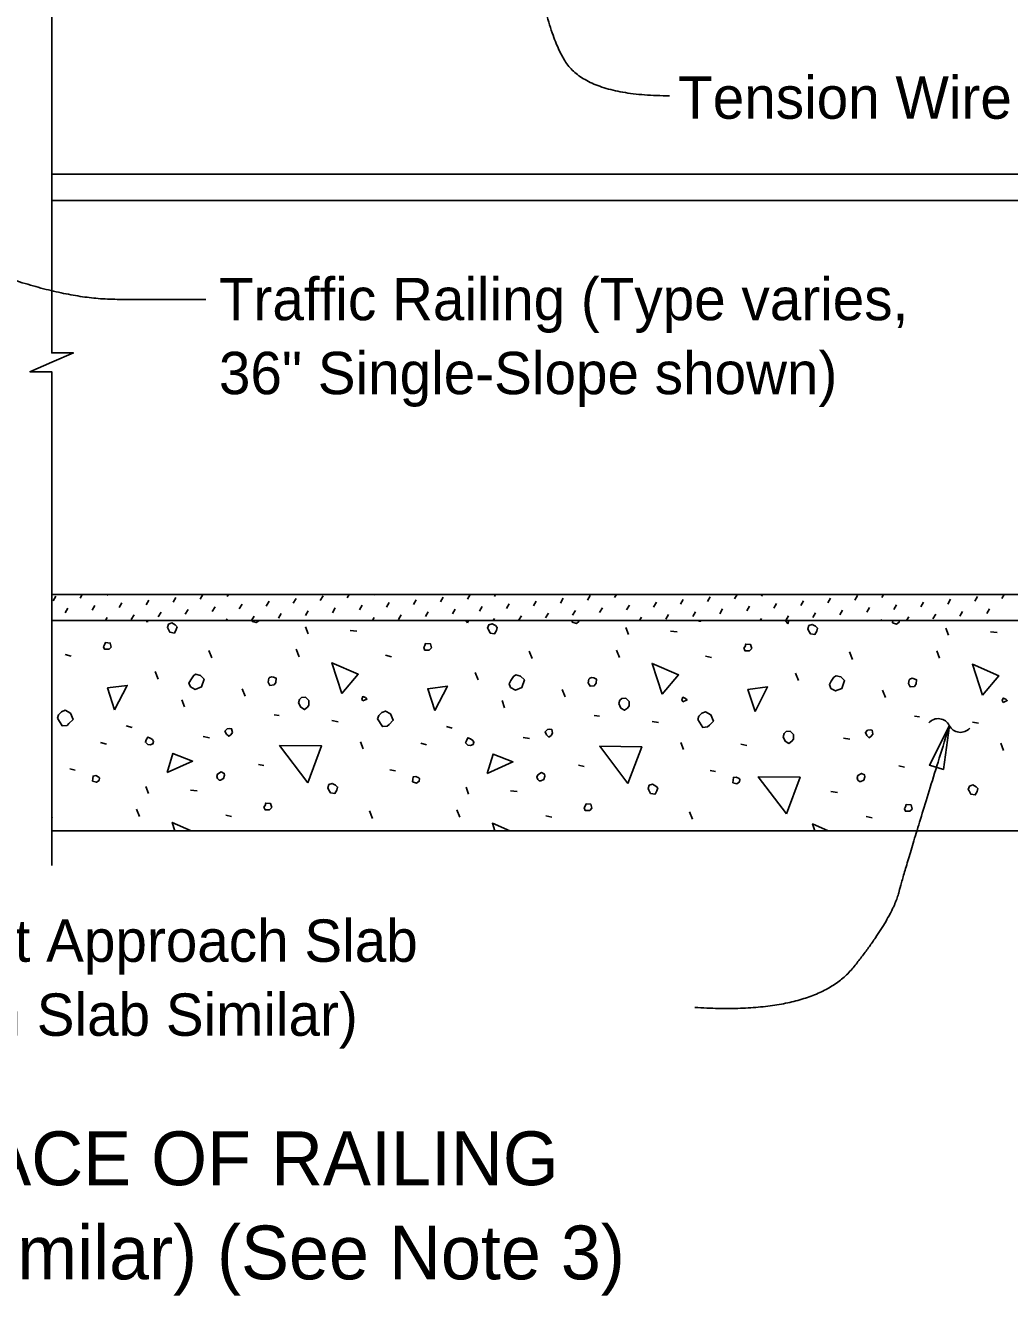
# Model space of a CAD drawing. Extents: x 0 to 41.1, y 0 to 25.9.
# Drawn here: x 16.13 to 20.81, y 10.89 to 16.93 of the extents above; entities that cross this region are included whole.
import ezdxf

# ---------------------------------------------------------------- set-up
doc = ezdxf.new("R2010")
doc.units = 0
for name, color, linetype in [('Dimension', 7, 'Continuous'), ('Miscellaneous', 7, 'Continuous'), ('SupstrConc', 7, 'Continuous'), ('TextStructures', 7, 'Continuous')]:
    doc.layers.add(name, color=color, linetype=linetype)

msp = doc.modelspace()

# ---------------------------------------------------------------- linework, layer by layer
at = {"layer": 'Dimension'}
msp.add_lwpolyline([(16.252, 17.2246), (16.252, 15.3737), (16.3553, 15.3737), (16.252, 15.3287), (16.1487, 15.2837), (16.252, 15.2837), (16.252, 12.9339)], dxfattribs=at)
msp.add_lwpolyline([(20.5246, 13.6005), (20.4289, 13.4122), (20.4962, 13.3912)], close=True, dxfattribs=at)
for centre, start, end in [((20.4706, 13.5736), 26.84133, 138.56855), ((20.577, 13.6275), 206.84133, 318.56855)]:
    msp.add_arc(centre, 0.0596, start, end, dxfattribs=at)
for points in [[(19.1927, 16.5972), (18.7949, 16.5972), (18.5909, 16.9342), (18.5297, 17.3911)], [(16.9853, 15.6282), (16.9154, 15.6282), (16.2159, 15.6282), (15.6583, 15.8852)], [(19.3131, 12.2588), (19.886, 12.2223), (20.2509, 12.679), (20.3172, 12.9363), (20.5245, 13.6004)]]:
    msp.add_open_spline(points, degree=2, dxfattribs=at)
at = {"layer": 'Miscellaneous'}
for p, q in [((16.2587, 14.1938), (16.2717, 14.2162)), ((16.3872, 14.2068), (16.3975, 14.2245)), ((16.5157, 14.2197), (16.5184, 14.2245)), ((16.8303, 14.1879), (16.8433, 14.2103)), ((16.9588, 14.2009), (16.9717, 14.2233)), ((17.0872, 14.2138), (17.0934, 14.2245)), ((17.5303, 14.195), (17.5433, 14.2174)), ((17.6588, 14.2079), (17.6684, 14.2245)), ((17.7873, 14.2209), (17.7893, 14.2245)), ((18.1019, 14.1891), (18.1149, 14.2115)), ((18.2304, 14.2021), (18.2433, 14.2244)), ((18.3588, 14.215), (18.3643, 14.2245)), ((18.6735, 14.1832), (18.6865, 14.2056)), ((18.802, 14.1962), (18.8149, 14.2186)), ((18.9304, 14.2091), (18.9393, 14.2245)), ((19.0589, 14.2221), (19.0603, 14.2245)), ((19.3735, 14.1903), (19.3865, 14.2127)), ((19.502, 14.2032), (19.5143, 14.2245)), ((19.6305, 14.2162), (19.6353, 14.2245)), ((19.9451, 14.1844), (19.9581, 14.2068)), ((20.0736, 14.1973), (20.0865, 14.2197)), ((20.202, 14.2103), (20.2103, 14.2245)), ((20.3305, 14.2233), (20.3312, 14.2245)), ((20.6452, 14.1914), (20.6581, 14.2138)), ((20.7736, 14.2044), (20.7852, 14.2245)), ((16.3165, 14.1361), (16.3294, 14.1584)), ((16.4449, 14.149), (16.4579, 14.1714)), ((16.5734, 14.162), (16.5864, 14.1844)), ((16.7019, 14.1749), (16.7148, 14.1973)), ((16.8881, 14.1302), (16.901, 14.1526)), ((17.0165, 14.1431), (17.0295, 14.1655)), ((17.145, 14.1561), (17.1579, 14.1785)), ((17.2734, 14.1691), (17.2864, 14.1914)), ((17.4019, 14.182), (17.4149, 14.2044)), ((17.4596, 14.1243), (17.4726, 14.1467)), ((17.5881, 14.1372), (17.6011, 14.1596)), ((17.7166, 14.1502), (17.7295, 14.1726)), ((17.845, 14.1632), (17.858, 14.1856)), ((17.9735, 14.1761), (17.9864, 14.1985)), ((18.1597, 14.1313), (18.1726, 14.1537)), ((18.2881, 14.1443), (18.3011, 14.1667)), ((18.4166, 14.1573), (18.4296, 14.1797)), ((18.545, 14.1702), (18.558, 14.1926)), ((18.7313, 14.1254), (18.7442, 14.1478)), ((18.8597, 14.1384), (18.8727, 14.1608)), ((18.9882, 14.1514), (19.0011, 14.1738)), ((19.1166, 14.1643), (19.1296, 14.1867)), ((19.2451, 14.1773), (19.258, 14.1997)), ((19.4313, 14.1325), (19.4443, 14.1549)), ((19.5597, 14.1455), (19.5727, 14.1679)), ((19.6882, 14.1584), (19.7012, 14.1808)), ((19.8167, 14.1714), (19.8296, 14.1938)), ((20.0029, 14.1266), (20.0158, 14.149)), ((20.1313, 14.1396), (20.1443, 14.162)), ((20.2598, 14.1526), (20.2727, 14.1749)), ((20.3882, 14.1655), (20.4012, 14.1879)), ((20.5167, 14.1785), (20.5297, 14.2009)), ((20.7029, 14.1337), (20.7159, 14.1561)), ((16.5075, 14.0995), (16.5157, 14.1137)), ((16.6311, 14.1042), (16.6441, 14.1266)), ((16.7596, 14.1172), (16.7726, 14.1396)), ((17.0825, 14.0995), (17.0872, 14.1078)), ((17.2034, 14.0995), (17.2157, 14.1207)), ((17.3312, 14.1113), (17.3441, 14.1337)), ((17.6574, 14.0995), (17.6588, 14.1019)), ((17.7784, 14.0995), (17.7873, 14.1148)), ((17.9028, 14.1054), (17.9157, 14.1278)), ((18.0312, 14.1184), (18.0442, 14.1408)), ((18.3534, 14.0995), (18.3588, 14.1089)), ((18.4743, 14.0995), (18.4873, 14.1219)), ((18.6028, 14.1125), (18.6158, 14.1349)), ((19.0493, 14.0995), (19.0589, 14.116)), ((19.1744, 14.1066), (19.1873, 14.129)), ((19.3028, 14.1196), (19.3158, 14.1419)), ((19.6243, 14.0995), (19.6305, 14.1101)), ((19.746, 14.1007), (19.7589, 14.1231)), ((19.8744, 14.1137), (19.8874, 14.1361)), ((20.1993, 14.0995), (20.202, 14.1042)), ((20.3203, 14.0995), (20.3305, 14.1172)), ((20.446, 14.1078), (20.459, 14.1302)), ((20.5744, 14.1207), (20.5874, 14.1431)), ((17.4727, 14.0371), (17.4603, 14.0707)), ((17.6725, 14.053), (17.7043, 14.0495)), ((18.9965, 14.0336), (18.9841, 14.0672)), ((19.1963, 14.0495), (19.2281, 14.046)), ((20.5203, 14.03), (20.508, 14.0636)), ((20.7201, 14.046), (20.7519, 14.0424)), ((17.4303, 13.9275), (17.4161, 13.9629)), ((16.3166, 13.9381), (16.3449, 13.931)), ((17.0148, 13.9222), (17.0007, 13.9576)), ((17.8404, 13.9346), (17.8687, 13.9275)), ((18.5387, 13.9187), (18.5245, 13.954)), ((18.9541, 13.924), (18.9399, 13.9593)), ((19.3642, 13.931), (19.3925, 13.924)), ((20.0625, 13.9151), (20.0483, 13.9505)), ((20.4779, 13.9204), (20.4638, 13.9558)), ((16.7585, 13.8214), (16.7444, 13.8568)), ((18.2823, 13.8179), (18.2682, 13.8533)), ((19.8062, 13.8144), (19.792, 13.8497)), ((16.884, 13.6889), (16.8717, 13.7225)), ((17.1722, 13.7401), (17.158, 13.7755)), ((18.696, 13.7366), (18.6819, 13.7719)), ((20.2198, 13.7331), (20.2057, 13.7684)), ((18.4078, 13.6853), (18.3955, 13.7189)), ((17.3101, 13.6517), (17.3348, 13.6482)), ((17.5858, 13.6235), (17.6159, 13.6182)), ((18.8339, 13.6482), (18.8586, 13.6447)), ((19.1097, 13.6199), (19.1397, 13.6146)), ((20.3577, 13.6447), (20.3824, 13.6411)), ((20.6335, 13.6164), (20.6635, 13.6111)), ((16.6065, 13.5987), (16.6348, 13.5916)), ((16.9724, 13.5474), (17.0025, 13.5421)), ((18.1303, 13.5952), (18.1586, 13.5881)), ((18.4962, 13.5439), (18.5263, 13.5386)), ((20.0201, 13.5404), (20.0501, 13.5351)), ((16.4845, 13.5192), (16.5128, 13.5121)), ((17.7343, 13.4891), (17.722, 13.5227)), ((18.0083, 13.5156), (18.0366, 13.5086)), ((19.2581, 13.4856), (19.2458, 13.5192)), ((19.5321, 13.5121), (19.5604, 13.505)), ((20.782, 13.482), (20.7696, 13.5156)), ((16.3378, 13.3936), (16.3643, 13.3883)), ((17.2358, 13.4149), (17.2623, 13.4096)), ((17.8616, 13.3901), (17.8881, 13.3848)), ((18.7596, 13.4113), (18.7862, 13.406)), ((19.3854, 13.3866), (19.4119, 13.3813)), ((20.2834, 13.4078), (20.31, 13.4025)), ((16.7126, 13.277), (16.7002, 13.3106)), ((18.2364, 13.2734), (18.224, 13.307)), ((16.9123, 13.2929), (16.9441, 13.2893)), ((18.4361, 13.2893), (18.468, 13.2858)), ((19.9599, 13.2858), (19.9918, 13.2823)), ((16.6701, 13.1674), (16.656, 13.2027)), ((17.7785, 13.1585), (17.7644, 13.1939)), ((18.1939, 13.1638), (18.1798, 13.1992)), ((19.3023, 13.155), (19.2882, 13.1904)), ((16.2547, 13.1621), (16.252, 13.1689)), ((17.0803, 13.1744), (17.1085, 13.1674)), ((18.6041, 13.1709), (18.6324, 13.1638)), ((20.1279, 13.1674), (20.1562, 13.1603))]:
    msp.add_line(p, q, dxfattribs=at)
for points in [[(16.7073, 14.0919), (16.7015, 14.0995)], [(16.7101, 14.0995), (16.7073, 14.0919)], [(16.8063, 14.0601), (16.8151, 14.0442), (16.8363, 14.0406), (16.8451, 14.0566), (16.8487, 14.0707), (16.8398, 14.0795), (16.8239, 14.0884), (16.808, 14.0831), (16.8027, 14.0672), (16.8063, 14.0601)], [(17.2058, 14.0954), (17.2252, 14.0901), (17.2376, 14.099), (17.2377, 14.0995)], [(17.2063, 14.0995), (17.2058, 14.0954)], [(18.2311, 14.0884), (18.2226, 14.0995)], [(18.2352, 14.0995), (18.2311, 14.0884)], [(18.3301, 14.0566), (18.3389, 14.0406), (18.3601, 14.0371), (18.369, 14.053), (18.3725, 14.0672), (18.3637, 14.076), (18.3477, 14.0848), (18.3318, 14.0795), (18.3265, 14.0636), (18.3301, 14.0566)], [(18.7296, 14.0919), (18.749, 14.0866), (18.7614, 14.0954), (18.762, 14.0995)], [(18.7307, 14.0995), (18.7296, 14.0919)], [(19.3301, 14.0995), (19.3324, 14.0972)], [(19.3324, 14.0972), (19.3395, 14.0972), (19.3441, 14.0995)], [(19.7549, 14.0848), (19.7437, 14.0995)], [(19.7604, 14.0995), (19.7549, 14.0848)], [(20.2534, 14.0884), (20.2728, 14.0831), (20.2852, 14.0919), (20.2863, 14.0995)], [(20.255, 14.0995), (20.2534, 14.0884)], [(19.8539, 14.053), (19.8627, 14.0371), (19.8839, 14.0336), (19.8928, 14.0495), (19.8963, 14.0636), (19.8875, 14.0725), (19.8716, 14.0813), (19.8556, 14.076), (19.8503, 14.0601), (19.8539, 14.053)], [(16.504, 13.9629), (16.5252, 13.9629), (16.5358, 13.9735), (16.5305, 13.9929), (16.5075, 13.9947), (16.504, 13.9841), (16.4987, 13.9752), (16.504, 13.9629), (16.5004, 13.9664)], [(18.0278, 13.9593), (18.049, 13.9593), (18.0596, 13.9699), (18.0543, 13.9894), (18.0313, 13.9912), (18.0278, 13.9805), (18.0225, 13.9717), (18.0278, 13.9593), (18.0242, 13.9629)], [(19.5516, 13.9558), (19.5728, 13.9558), (19.5834, 13.9664), (19.5781, 13.9858), (19.5551, 13.9876), (19.5516, 13.977), (19.5463, 13.9682), (19.5516, 13.9558), (19.5481, 13.9593)], [(16.9123, 13.7843), (16.9353, 13.7719), (16.9654, 13.7843), (16.9777, 13.8214), (16.96, 13.8391), (16.9371, 13.8444), (16.9265, 13.8374), (16.9141, 13.8179), (16.9052, 13.802), (16.9123, 13.7843)], [(17.6336, 13.7525), (17.5858, 13.8992), (17.7113, 13.8444), (17.6336, 13.7525)], [(19.1574, 13.749), (19.1097, 13.8957), (19.2352, 13.8409), (19.1574, 13.749)], [(20.6812, 13.7454), (20.6335, 13.8922), (20.759, 13.8374), (20.6812, 13.7454)], [(16.5517, 13.6747), (16.5181, 13.779), (16.6118, 13.7914), (16.5517, 13.6747)], [(17.2818, 13.8073), (17.2906, 13.7914), (17.3101, 13.7932), (17.3189, 13.8055), (17.3207, 13.825), (17.3083, 13.8303), (17.2995, 13.8321), (17.2889, 13.8285), (17.2853, 13.825), (17.2818, 13.8073)], [(18.0755, 13.6712), (18.0419, 13.7755), (18.1356, 13.7879), (18.0755, 13.6712)], [(18.4361, 13.7808), (18.4591, 13.7684), (18.4892, 13.7808), (18.5015, 13.8179), (18.4839, 13.8356), (18.4609, 13.8409), (18.4503, 13.8338), (18.4379, 13.8144), (18.4291, 13.7985), (18.4361, 13.7808)], [(18.8056, 13.8038), (18.8144, 13.7879), (18.8339, 13.7896), (18.8427, 13.802), (18.8445, 13.8214), (18.8321, 13.8267), (18.8233, 13.8285), (18.8127, 13.825), (18.8091, 13.8214), (18.8056, 13.8038)], [(19.5993, 13.6677), (19.5657, 13.7719), (19.6594, 13.7843), (19.5993, 13.6677)], [(19.9599, 13.7773), (19.9829, 13.7649), (20.013, 13.7773), (20.0254, 13.8144), (20.0077, 13.8321), (19.9847, 13.8374), (19.9741, 13.8303), (19.9617, 13.8108), (19.9529, 13.7949), (19.9599, 13.7773)], [(20.3294, 13.8002), (20.3382, 13.7843), (20.3577, 13.7861), (20.3665, 13.7985), (20.3683, 13.8179), (20.3559, 13.8232), (20.3471, 13.825), (20.3365, 13.8214), (20.3329, 13.8179), (20.3294, 13.8002)], [(17.4267, 13.7083), (17.4373, 13.6871), (17.455, 13.6765), (17.4692, 13.6871), (17.4762, 13.6977), (17.4762, 13.7189), (17.4603, 13.7348), (17.4409, 13.7331), (17.432, 13.7242), (17.4267, 13.7083)], [(17.7326, 13.7171), (17.752, 13.726), (17.7449, 13.7331), (17.7326, 13.7384), (17.7273, 13.726), (17.7326, 13.7171)], [(18.9506, 13.7048), (18.9612, 13.6836), (18.9788, 13.673), (18.993, 13.6836), (19.0001, 13.6942), (19.0001, 13.7154), (18.9841, 13.7313), (18.9647, 13.7295), (18.9559, 13.7207), (18.9506, 13.7048)], [(19.2564, 13.7136), (19.2758, 13.7225), (19.2688, 13.7295), (19.2564, 13.7348), (19.2511, 13.7225), (19.2564, 13.7136)], [(20.7802, 13.7101), (20.7996, 13.7189), (20.7926, 13.726), (20.7802, 13.7313), (20.7749, 13.7189), (20.7802, 13.7101)], [(16.2795, 13.6358), (16.3024, 13.5987), (16.3254, 13.6005), (16.3343, 13.6093), (16.3537, 13.6288), (16.3413, 13.6588), (16.3166, 13.673), (16.2989, 13.6659), (16.2848, 13.6517), (16.2795, 13.6358)], [(17.8033, 13.6323), (17.8263, 13.5952), (17.8492, 13.5969), (17.8581, 13.6058), (17.8775, 13.6252), (17.8651, 13.6553), (17.8404, 13.6694), (17.8227, 13.6623), (17.8086, 13.6482), (17.8033, 13.6323)], [(19.3271, 13.6288), (19.3501, 13.5916), (19.373, 13.5934), (19.3819, 13.6022), (19.4013, 13.6217), (19.389, 13.6517), (19.3642, 13.6659), (19.3465, 13.6588), (19.3324, 13.6447), (19.3271, 13.6288)], [(16.709, 13.5103), (16.7214, 13.5086), (16.7338, 13.5139), (16.7373, 13.5245), (16.732, 13.5333), (16.7214, 13.5404), (16.709, 13.5457), (16.702, 13.5315), (16.6984, 13.5209), (16.709, 13.5103)], [(17.0838, 13.5598), (17.0944, 13.5492), (17.105, 13.5563), (17.1121, 13.5669), (17.1085, 13.5846), (17.0997, 13.5863), (17.0873, 13.5846), (17.0767, 13.574), (17.0838, 13.5598)], [(18.2328, 13.5068), (18.2452, 13.505), (18.2576, 13.5103), (18.2611, 13.5209), (18.2558, 13.5298), (18.2452, 13.5368), (18.2328, 13.5421), (18.2258, 13.528), (18.2222, 13.5174), (18.2328, 13.5068)], [(18.6076, 13.5563), (18.6182, 13.5457), (18.6288, 13.5527), (18.6359, 13.5634), (18.6324, 13.581), (18.6235, 13.5828), (18.6111, 13.581), (18.6005, 13.5704), (18.6076, 13.5563)], [(19.7325, 13.5466), (19.7431, 13.5254), (19.7608, 13.5148), (19.7749, 13.5254), (19.782, 13.536), (19.782, 13.5572), (19.7661, 13.5731), (19.7467, 13.5713), (19.7378, 13.5625), (19.7325, 13.5466)], [(20.1314, 13.5527), (20.142, 13.5421), (20.1526, 13.5492), (20.1597, 13.5598), (20.1562, 13.5775), (20.1473, 13.5793), (20.135, 13.5775), (20.1244, 13.5669), (20.1314, 13.5527)], [(17.4709, 13.3282), (17.3366, 13.505), (17.5363, 13.5032), (17.4709, 13.3282)], [(18.9947, 13.3247), (18.8604, 13.5015), (19.0602, 13.4997), (18.9947, 13.3247)], [(16.8009, 13.376), (16.8292, 13.4679), (16.9229, 13.4308), (16.8009, 13.376)], [(18.3248, 13.3724), (18.353, 13.4644), (18.4467, 13.4272), (18.3248, 13.3724)], [(16.4456, 13.3353), (16.4651, 13.33), (16.4774, 13.3388), (16.4792, 13.3512), (16.4757, 13.3548), (16.4615, 13.3618), (16.4492, 13.3601), (16.4474, 13.3477), (16.4456, 13.3353)], [(17.0484, 13.3406), (17.0555, 13.3406), (17.0696, 13.3477), (17.075, 13.3636), (17.0732, 13.3724), (17.059, 13.3795), (17.0414, 13.3689), (17.0378, 13.3583), (17.0414, 13.3477), (17.0484, 13.3406)], [(17.9694, 13.3318), (17.9889, 13.3265), (18.0013, 13.3353), (18.003, 13.3477), (17.9995, 13.3512), (17.9854, 13.3583), (17.973, 13.3565), (17.9712, 13.3441), (17.9694, 13.3318)], [(18.5723, 13.3371), (18.5793, 13.3371), (18.5935, 13.3441), (18.5988, 13.3601), (18.597, 13.3689), (18.5829, 13.376), (18.5652, 13.3654), (18.5616, 13.3548), (18.5652, 13.3441), (18.5723, 13.3371)], [(20.0961, 13.3335), (20.1031, 13.3335), (20.1173, 13.3406), (20.1226, 13.3565), (20.1208, 13.3654), (20.1067, 13.3724), (20.089, 13.3618), (20.0855, 13.3512), (20.089, 13.3406), (20.0961, 13.3335)], [(17.5699, 13.2964), (17.5788, 13.2805), (17.6, 13.277), (17.6088, 13.2929), (17.6124, 13.307), (17.6035, 13.3159), (17.5876, 13.3247), (17.5717, 13.3194), (17.5664, 13.3035), (17.5699, 13.2964)], [(19.0937, 13.2929), (19.1026, 13.277), (19.1238, 13.2734), (19.1326, 13.2893), (19.1362, 13.3035), (19.1273, 13.3123), (19.1114, 13.3212), (19.0955, 13.3159), (19.0902, 13.3), (19.0937, 13.2929)], [(19.4933, 13.3282), (19.5127, 13.3229), (19.5251, 13.3318), (19.5268, 13.3441), (19.5233, 13.3477), (19.5092, 13.3548), (19.4968, 13.353), (19.495, 13.3406), (19.4933, 13.3282)], [(19.7486, 13.1794), (19.6143, 13.3562), (19.814, 13.3544), (19.7486, 13.1794)], [(20.6176, 13.2893), (20.6264, 13.2734), (20.6476, 13.2699), (20.6564, 13.2858), (20.66, 13.3), (20.6511, 13.3088), (20.6352, 13.3176), (20.6193, 13.3123), (20.614, 13.2964), (20.6176, 13.2893)], [(17.2676, 13.1992), (17.2889, 13.1992), (17.2995, 13.2098), (17.2942, 13.2292), (17.2712, 13.231), (17.2676, 13.2204), (17.2623, 13.2116), (17.2676, 13.1992), (17.2641, 13.2027)], [(18.7915, 13.1957), (18.8127, 13.1957), (18.8233, 13.2063), (18.818, 13.2257), (18.795, 13.2275), (18.7915, 13.2169), (18.7862, 13.208), (18.7915, 13.1957), (18.7879, 13.1992)], [(20.3153, 13.1921), (20.3365, 13.1921), (20.3471, 13.2027), (20.3418, 13.2222), (20.3188, 13.2239), (20.3153, 13.2133), (20.31, 13.2045), (20.3153, 13.1921), (20.3117, 13.1957)], [(16.8386, 13.0995), (16.8257, 13.1391), (16.9163, 13.0995)], [(18.3612, 13.0995), (18.3495, 13.1356), (18.432, 13.0995)], [(19.8839, 13.0995), (19.8733, 13.132), (19.9477, 13.0995)]]:
    msp.add_lwpolyline(points, dxfattribs=at)
at = {"layer": 'SupstrConc'}
for p, q in [((16.252, 16.2245), (23.5538, 16.2245)), ((16.252, 16.0995), (23.5538, 16.0995)), ((16.252, 14.2245), (23.5538, 14.2245)), ((21.5538, 14.0995), (16.252, 14.0995)), ((21.9365, 13.0995), (16.252, 13.0995))]:
    msp.add_line(p, q, dxfattribs=at)

# ---------------------------------------------------------------- texts
at = {"layer": 'Dimension'}
for s, height, p in [('Traffic Railing (Type varies,', 0.2016, (17.0479, 15.5291)), ('36" Single-Slope shown)', 0.2016, (17.0479, 15.1771)), ('Approach Slab (Flexible Pavement Approach Slab ', 0.2016, (11.9999, 12.4759)), ('Shown, Rigid Pavement Approach Slab Similar)', 0.2016, (11.9999, 12.1239)), ('ELEVATION OF OUTSIDE FACE OF RAILING', 0.256001, (11.5134, 11.4128)), ('(Traffic Railing Shown, Concrete Parapet Similar) (See Note 3)', 0.256001, (9.4668, 10.9648))]:
    msp.add_text(s, height=height, dxfattribs=at).set_placement(p)
at = {"layer": 'TextStructures'}
msp.add_text('Tension Wire', height=0.2016, dxfattribs=at).set_placement((19.2335, 16.4877))

doc.saveas('drawing.dxf')
